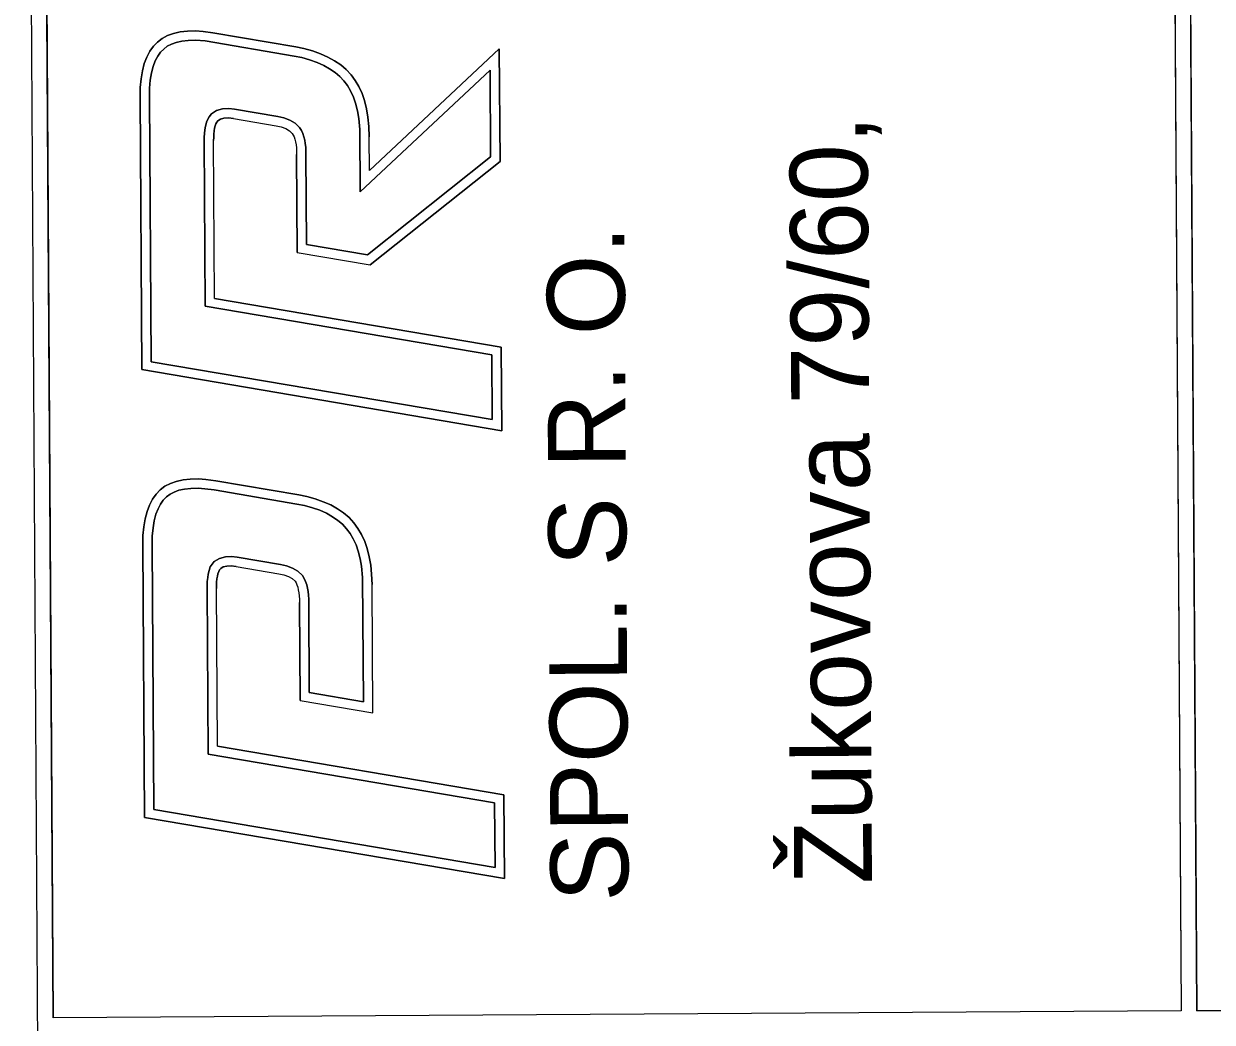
# Model space of a CAD drawing. Extents: x -735036 to -734743, y -1144813 to -1144181.
# Drawn here: x -734819.2 to -734790.17, y -1144246.26 to -1144221.87 of the extents above; entities that cross this region are included whole.
import ezdxf

# ---------------------------------------------------------------- set-up
doc = ezdxf.new("R2010")
doc.units = 0
doc.layers.add('000_rozpiska', color=7, linetype='Continuous')

# ---------------------------------------------------------------- blocks, each defined once
blk = doc.blocks.new('A$C2B726605')
at = {"layer": '000_rozpiska'}
for p, q in [((-8.894, 71.716), (-181.794, 71.716)), ((-8.894, 71.716), (-181.794, 71.716)), ((-8.894, 71.336), (-63.044, 71.336)), ((-63.044, 43.784), (-63.044, 71.336)), ((-59.709, 60.291), (-58.162, 69.071)), ((-58.164, 69.072), (-51.5, 69.072)), ((-48.767, 60.291), (-47.22, 69.071)), ((-47.222, 69.072), (-40.558, 69.072)), ((-56.434, 67.282), (-57.665, 60.291)), ((-56.434, 67.282), (-52.576, 67.282)), ((-49.947, 67.282), (-50.304, 65.256)), ((-45.492, 67.282), (-46.723, 60.291)), ((-45.492, 67.282), (-41.634, 67.282)), ((-39.005, 67.282), (-39.362, 65.256)), ((-52.042, 66.796), (-52.226, 65.755)), ((-41.1, 66.796), (-41.284, 65.755)), ((-55.325, 65.256), (-55.638, 63.481)), ((-55.325, 65.256), (-52.933, 65.256)), ((-44.383, 65.256), (-44.696, 63.481)), ((-44.383, 65.256), (-41.991, 65.256)), ((-55.638, 63.481), (-52.508, 63.481)), ((-42.191, 60.291), (-44.696, 63.481)), ((-42.389, 63.481), (-41.567, 63.481)), ((-39.439, 60.291), (-42.389, 63.481)), ((-57.665, 60.291), (-59.709, 60.291)), ((-46.723, 60.291), (-48.767, 60.291)), ((-39.439, 60.291), (-42.191, 60.291)), ((-6.424, 43.784), (-63.044, 43.784)), ((-63.044, 43.404), (-63.044, 22.504)), ((-6.424, 43.404), (-63.044, 43.404))]:
    blk.add_line(p, q, dxfattribs=at)
for points in [[(-63.044, 43.784), (-63.044, 71.336), (-8.894, 71.336)], [(-6.424, 68.866), (-6.424, 43.784), (-63.044, 43.784)], [(-50.687, 68.963), (-50.864, 69.011), (-51.061, 69.045), (-51.275, 69.066), (-51.5, 69.072), (-58.162, 69.072), (-59.709, 60.291), (-57.665, 60.291), (-56.434, 67.282), (-52.576, 67.282), (-52.505, 67.28), (-52.422, 67.276), (-52.344, 67.267), (-52.276, 67.256), (-52.217, 67.241), (-52.168, 67.222), (-52.127, 67.2), (-52.095, 67.174), (-52.054, 67.111), (-52.032, 67.026), (-52.029, 66.916), (-52.042, 66.796), (-52.226, 65.755), (-52.255, 65.629), (-52.298, 65.515), (-52.35, 65.426), (-52.415, 65.36), (-52.455, 65.336), (-52.502, 65.314), (-52.56, 65.295), (-52.624, 65.281), (-52.698, 65.269), (-52.772, 65.261), (-52.862, 65.257), (-52.933, 65.256), (-55.325, 65.256), (-55.638, 63.481), (-52.508, 63.481), (-52.255, 63.488), (-52.029, 63.509), (-51.827, 63.542), (-51.622, 63.593), (-51.452, 63.651), (-51.281, 63.729), (-51.133, 63.816), (-50.997, 63.915), (-50.866, 64.032), (-50.752, 64.167), (-50.649, 64.314), (-50.556, 64.477), (-50.474, 64.657), (-50.402, 64.856), (-50.345, 65.063), (-50.304, 65.256), (-49.947, 67.282), (-49.913, 67.52), (-49.899, 67.704), (-49.903, 67.903), (-49.918, 68.079), (-49.956, 68.245), (-50.007, 68.389), (-50.075, 68.522), (-50.163, 68.638), (-50.267, 68.739), (-50.389, 68.827), (-50.531, 68.902), (-50.687, 68.963)], [(-57.971, 68.844), (-51.507, 68.844), (-51.29, 68.838), (-51.091, 68.819), (-50.914, 68.788), (-50.758, 68.746), (-50.626, 68.695), (-50.51, 68.633), (-50.414, 68.564), (-50.335, 68.487), (-50.269, 68.4), (-50.217, 68.298), (-50.175, 68.181), (-50.144, 68.044), (-50.131, 67.891), (-50.127, 67.711), (-50.14, 67.545), (-50.172, 67.318), (-50.527, 65.303), (-50.567, 65.117), (-50.62, 64.925), (-50.685, 64.743), (-50.759, 64.581), (-50.842, 64.437), (-50.933, 64.306), (-51.03, 64.192), (-51.141, 64.092), (-51.258, 64.007), (-51.386, 63.932), (-51.537, 63.863), (-51.686, 63.812), (-51.873, 63.766), (-52.059, 63.735), (-52.334, 63.709), (-55.366, 63.709), (-55.134, 65.028), (-52.929, 65.028), (-52.855, 65.029), (-52.755, 65.034), (-52.668, 65.043), (-52.581, 65.056), (-52.499, 65.075), (-52.418, 65.102), (-52.348, 65.135), (-52.272, 65.18), (-52.168, 65.287), (-52.092, 65.417), (-52.036, 65.563), (-52.002, 65.71), (-51.816, 66.77), (-51.8, 66.907), (-51.805, 67.058), (-51.843, 67.204), (-51.923, 67.328), (-52.052, 67.434), (-52.229, 67.479), (-52.312, 67.493), (-52.404, 67.503), (-52.497, 67.508), (-52.57, 67.51), (-56.625, 67.51), (-57.857, 60.519), (-59.437, 60.519), (-57.971, 68.844)], [(-50.144, 68.044), (-50.175, 68.181), (-50.217, 68.298), (-50.269, 68.4), (-50.335, 68.487), (-50.414, 68.564), (-50.51, 68.633), (-50.626, 68.695), (-50.758, 68.746), (-50.914, 68.788), (-51.091, 68.819), (-51.29, 68.838), (-51.507, 68.844), (-57.971, 68.844), (-59.437, 60.519), (-57.857, 60.519), (-56.625, 67.51), (-52.57, 67.51), (-52.497, 67.508), (-52.404, 67.503), (-52.312, 67.493), (-52.229, 67.479), (-52.052, 67.434), (-51.923, 67.328), (-51.843, 67.204), (-51.805, 67.058), (-51.8, 66.907), (-51.816, 66.77), (-52.002, 65.71), (-52.036, 65.563), (-52.092, 65.417), (-52.168, 65.287), (-52.272, 65.18), (-52.348, 65.135), (-52.418, 65.102), (-52.499, 65.075), (-52.581, 65.056), (-52.668, 65.043), (-52.755, 65.034), (-52.855, 65.029), (-52.929, 65.028), (-55.134, 65.028), (-55.366, 63.709), (-52.334, 63.709), (-52.059, 63.735), (-51.873, 63.766), (-51.686, 63.812), (-51.537, 63.863), (-51.386, 63.932), (-51.258, 64.007), (-51.141, 64.092), (-51.03, 64.192), (-50.933, 64.306), (-50.842, 64.437), (-50.759, 64.581), (-50.685, 64.743), (-50.62, 64.925), (-50.567, 65.117), (-50.527, 65.303), (-50.172, 67.318), (-50.14, 67.545), (-50.127, 67.711), (-50.131, 67.891), (-50.144, 68.044)], [(-56.625, 67.51), (-57.857, 60.519), (-59.437, 60.519), (-57.971, 68.844), (-51.507, 68.844), (-51.29, 68.838), (-51.091, 68.819), (-50.914, 68.788), (-50.758, 68.746), (-50.626, 68.695), (-50.51, 68.633), (-50.414, 68.564), (-50.335, 68.487), (-50.269, 68.4), (-50.217, 68.298), (-50.175, 68.181), (-50.144, 68.044), (-50.131, 67.891), (-50.127, 67.711), (-50.14, 67.545), (-50.172, 67.318), (-50.527, 65.303), (-50.567, 65.117), (-50.62, 64.925), (-50.685, 64.743), (-50.759, 64.581), (-50.842, 64.437), (-50.933, 64.306), (-51.03, 64.192), (-51.141, 64.092), (-51.258, 64.007), (-51.386, 63.932), (-51.537, 63.863), (-51.686, 63.812), (-51.873, 63.766), (-52.059, 63.735), (-52.334, 63.709), (-55.366, 63.709), (-55.134, 65.028), (-52.929, 65.028), (-52.855, 65.029), (-52.755, 65.034), (-52.668, 65.043), (-52.581, 65.056), (-52.499, 65.075), (-52.418, 65.102), (-52.348, 65.135), (-52.272, 65.18), (-52.168, 65.287), (-52.092, 65.417), (-52.036, 65.563), (-52.002, 65.71), (-51.816, 66.77), (-51.8, 66.907), (-51.805, 67.058), (-51.843, 67.204), (-51.923, 67.328), (-52.052, 67.434), (-52.229, 67.479), (-52.312, 67.493), (-52.404, 67.503), (-52.497, 67.508), (-52.57, 67.51), (-56.625, 67.51)], [(-51.5, 69.072), (-51.275, 69.066), (-51.061, 69.045), (-50.864, 69.011), (-50.687, 68.963), (-50.531, 68.902), (-50.389, 68.827), (-50.267, 68.739), (-50.163, 68.638), (-50.075, 68.522), (-50.007, 68.389), (-49.956, 68.245), (-49.918, 68.079), (-49.903, 67.903), (-49.899, 67.704), (-49.913, 67.52), (-49.947, 67.282)], [(-38.971, 67.52), (-38.957, 67.704), (-38.961, 67.903), (-38.976, 68.079), (-39.014, 68.245), (-39.065, 68.389), (-39.133, 68.522), (-39.221, 68.638), (-39.325, 68.739), (-39.447, 68.827), (-39.589, 68.902), (-39.745, 68.963), (-39.922, 69.011), (-40.119, 69.045), (-40.333, 69.066), (-40.558, 69.072), (-47.22, 69.072), (-48.767, 60.291), (-46.723, 60.291), (-45.492, 67.282), (-41.634, 67.282), (-41.563, 67.28), (-41.48, 67.276), (-41.402, 67.267), (-41.334, 67.256), (-41.275, 67.241), (-41.226, 67.222), (-41.185, 67.2), (-41.153, 67.174), (-41.112, 67.111), (-41.09, 67.026), (-41.087, 66.916), (-41.1, 66.796), (-41.284, 65.755), (-41.313, 65.629), (-41.356, 65.515), (-41.408, 65.426), (-41.473, 65.36), (-41.513, 65.336), (-41.56, 65.314), (-41.618, 65.295), (-41.682, 65.281), (-41.756, 65.269), (-41.83, 65.261), (-41.92, 65.257), (-41.991, 65.256), (-44.383, 65.256), (-44.696, 63.481), (-42.191, 60.291), (-39.439, 60.291), (-42.389, 63.481), (-41.567, 63.481), (-41.313, 63.488), (-41.087, 63.509), (-40.885, 63.542), (-40.68, 63.593), (-40.51, 63.651), (-40.339, 63.729), (-40.191, 63.816), (-40.055, 63.915), (-39.924, 64.032), (-39.81, 64.167), (-39.707, 64.314), (-39.614, 64.477), (-39.532, 64.657), (-39.46, 64.856), (-39.403, 65.063), (-39.362, 65.256), (-39.005, 67.282), (-38.971, 67.52)], [(-45.683, 67.51), (-46.915, 60.519), (-48.495, 60.519), (-47.029, 68.844), (-40.565, 68.844), (-40.348, 68.838), (-40.149, 68.819), (-39.972, 68.788), (-39.817, 68.746), (-39.684, 68.695), (-39.568, 68.633), (-39.472, 68.564), (-39.393, 68.487), (-39.327, 68.4), (-39.275, 68.298), (-39.233, 68.181), (-39.202, 68.044), (-39.189, 67.891), (-39.185, 67.711), (-39.203, 67.472), (-39.585, 65.303), (-39.625, 65.117), (-39.678, 64.925), (-39.743, 64.743), (-39.817, 64.581), (-39.9, 64.437), (-39.991, 64.306), (-40.088, 64.192), (-40.199, 64.092), (-40.316, 64.007), (-40.444, 63.932), (-40.595, 63.863), (-40.744, 63.812), (-40.931, 63.766), (-41.117, 63.735), (-41.392, 63.709), (-42.91, 63.709), (-39.96, 60.519), (-42.08, 60.519), (-44.454, 63.542), (-44.192, 65.028), (-41.987, 65.028), (-41.913, 65.029), (-41.813, 65.034), (-41.726, 65.043), (-41.639, 65.056), (-41.557, 65.075), (-41.476, 65.102), (-41.406, 65.135), (-41.33, 65.18), (-41.226, 65.287), (-41.15, 65.417), (-41.094, 65.563), (-41.06, 65.71), (-40.874, 66.77), (-40.858, 66.907), (-40.863, 67.058), (-40.901, 67.204), (-40.981, 67.328), (-41.057, 67.39), (-41.162, 67.447), (-41.287, 67.479), (-41.37, 67.493), (-41.462, 67.503), (-41.555, 67.508), (-41.628, 67.51), (-45.683, 67.51)], [(-39.275, 68.298), (-39.327, 68.4), (-39.393, 68.487), (-39.472, 68.564), (-39.568, 68.633), (-39.684, 68.695), (-39.817, 68.746), (-39.972, 68.788), (-40.149, 68.819), (-40.348, 68.838), (-40.565, 68.844), (-47.029, 68.844), (-48.495, 60.519), (-46.915, 60.519), (-45.683, 67.51), (-41.628, 67.51), (-41.555, 67.508), (-41.462, 67.503), (-41.37, 67.493), (-41.287, 67.479), (-41.162, 67.447), (-41.057, 67.39), (-40.981, 67.328), (-40.901, 67.204), (-40.863, 67.058), (-40.858, 66.907), (-40.874, 66.77), (-41.06, 65.71), (-41.094, 65.563), (-41.15, 65.417), (-41.226, 65.287), (-41.33, 65.18), (-41.406, 65.135), (-41.476, 65.102), (-41.557, 65.075), (-41.639, 65.056), (-41.726, 65.043), (-41.813, 65.034), (-41.913, 65.029), (-41.987, 65.028), (-44.192, 65.028), (-44.454, 63.542), (-42.08, 60.519), (-39.96, 60.519), (-42.91, 63.709), (-41.392, 63.709), (-41.117, 63.735), (-40.931, 63.766), (-40.744, 63.812), (-40.595, 63.863), (-40.444, 63.932), (-40.316, 64.007), (-40.199, 64.092), (-40.088, 64.192), (-39.991, 64.306), (-39.9, 64.437), (-39.817, 64.581), (-39.743, 64.743), (-39.678, 64.925), (-39.625, 65.117), (-39.585, 65.303), (-39.203, 67.472), (-39.185, 67.711), (-39.189, 67.891), (-39.202, 68.044), (-39.233, 68.181), (-39.275, 68.298)], [(-45.683, 67.51), (-46.915, 60.519), (-48.495, 60.519), (-47.029, 68.844), (-40.565, 68.844), (-40.348, 68.838), (-40.149, 68.819), (-39.972, 68.788), (-39.817, 68.746), (-39.684, 68.695), (-39.568, 68.633), (-39.472, 68.564), (-39.393, 68.487), (-39.327, 68.4), (-39.275, 68.298), (-39.233, 68.181), (-39.202, 68.044), (-39.189, 67.891), (-39.185, 67.711), (-39.203, 67.472), (-39.585, 65.303), (-39.625, 65.117), (-39.678, 64.925), (-39.743, 64.743), (-39.817, 64.581), (-39.9, 64.437), (-39.991, 64.306), (-40.088, 64.192), (-40.199, 64.092), (-40.316, 64.007), (-40.444, 63.932), (-40.595, 63.863), (-40.744, 63.812), (-40.931, 63.766), (-41.117, 63.735), (-41.392, 63.709), (-42.91, 63.709), (-39.96, 60.519), (-42.08, 60.519), (-44.454, 63.542), (-44.192, 65.028), (-41.987, 65.028), (-41.913, 65.029), (-41.813, 65.034), (-41.726, 65.043), (-41.639, 65.056), (-41.557, 65.075), (-41.476, 65.102), (-41.406, 65.135), (-41.33, 65.18), (-41.226, 65.287), (-41.15, 65.417), (-41.094, 65.563), (-41.06, 65.71), (-40.874, 66.77), (-40.858, 66.907), (-40.863, 67.058), (-40.901, 67.204), (-40.981, 67.328), (-41.057, 67.39), (-41.162, 67.447), (-41.287, 67.479), (-41.37, 67.493), (-41.462, 67.503), (-41.555, 67.508), (-41.628, 67.51), (-45.683, 67.51)], [(-40.558, 69.072), (-40.333, 69.066), (-40.119, 69.045), (-39.922, 69.011), (-39.745, 68.963), (-39.589, 68.902), (-39.447, 68.827), (-39.325, 68.739), (-39.221, 68.638), (-39.133, 68.522), (-39.065, 68.389), (-39.014, 68.245), (-38.976, 68.079), (-38.961, 67.903), (-38.957, 67.704), (-38.971, 67.52), (-39.005, 67.282)], [(-52.217, 67.241), (-52.276, 67.256), (-52.344, 67.267), (-52.422, 67.276), (-52.505, 67.28), (-52.576, 67.282)], [(-52.042, 66.796), (-52.029, 66.916), (-52.032, 67.026), (-52.054, 67.111), (-52.095, 67.174), (-52.127, 67.2), (-52.168, 67.222), (-52.217, 67.241)], [(-41.275, 67.241), (-41.334, 67.256), (-41.402, 67.267), (-41.48, 67.276), (-41.563, 67.28), (-41.634, 67.282)], [(-41.1, 66.796), (-41.087, 66.916), (-41.09, 67.026), (-41.112, 67.111), (-41.153, 67.174), (-41.185, 67.2), (-41.226, 67.222), (-41.275, 67.241)], [(-52.226, 65.755), (-52.255, 65.629), (-52.298, 65.515), (-52.35, 65.426), (-52.415, 65.36), (-52.455, 65.336), (-52.502, 65.314), (-52.56, 65.295), (-52.624, 65.281), (-52.698, 65.269), (-52.772, 65.261), (-52.862, 65.257), (-52.933, 65.256)], [(-41.284, 65.755), (-41.313, 65.629), (-41.356, 65.515), (-41.408, 65.426), (-41.473, 65.36), (-41.513, 65.336), (-41.56, 65.314), (-41.618, 65.295), (-41.682, 65.281), (-41.756, 65.269), (-41.83, 65.261), (-41.92, 65.257), (-41.991, 65.256)], [(-50.304, 65.256), (-50.345, 65.063), (-50.402, 64.856), (-50.474, 64.657), (-50.556, 64.477), (-50.649, 64.314), (-50.752, 64.167), (-50.866, 64.032), (-50.997, 63.915), (-51.133, 63.816), (-51.281, 63.729), (-51.452, 63.651), (-51.622, 63.593), (-51.827, 63.542), (-52.029, 63.509), (-52.255, 63.488), (-52.508, 63.481)], [(-39.362, 65.256), (-39.403, 65.063), (-39.46, 64.856), (-39.532, 64.657), (-39.614, 64.477), (-39.707, 64.314), (-39.81, 64.167), (-39.924, 64.032), (-40.055, 63.915), (-40.191, 63.816), (-40.339, 63.729), (-40.51, 63.651), (-40.68, 63.593), (-40.885, 63.542), (-41.087, 63.509), (-41.313, 63.488), (-41.567, 63.481)], [(-63.044, 22.504), (-63.044, 43.404), (-6.424, 43.404), (-6.424, 22.504), (-63.044, 22.504)]]:
    blk.add_lwpolyline(points, dxfattribs=at)
for s, p in [('SPOL. S R. O.', (-60.29, 57.265)), ('Žukovova 79/60, ', (-59.898, 51.316))]:
    blk.add_text(s, height=1.9, dxfattribs=at).set_placement(p)

msp = doc.modelspace()

# ---------------------------------------------------------------- block references
at = {"layer": '000_rozpiska', "rotation": 90.35414249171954}
msp.add_blockref('A$C2B726605', (-734747.538, -1144182.67), dxfattribs=at)

doc.saveas('drawing.dxf')
